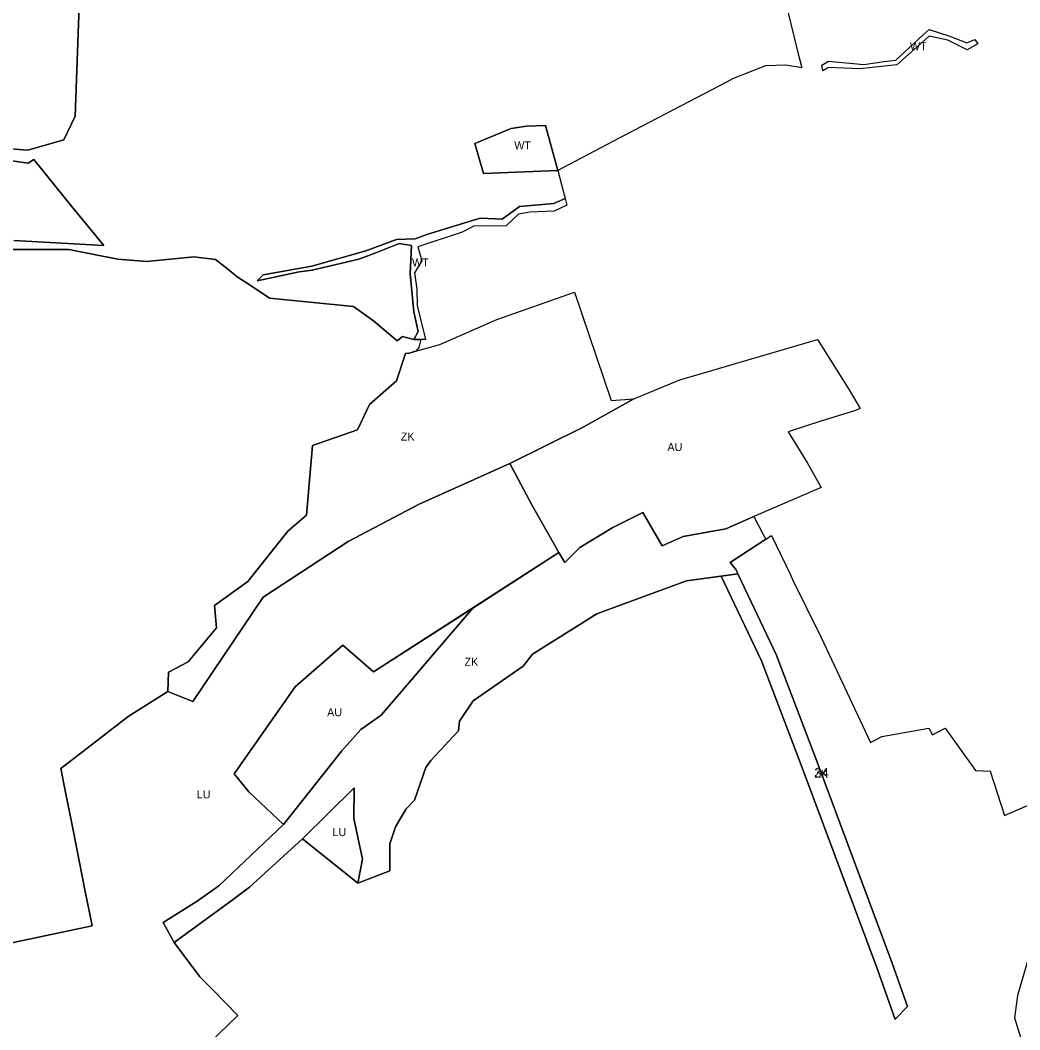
# Model space of a CAD drawing. Extents: x -521261 to -517465, y -1182764 to -1179456.
# Drawn here: x -520192 to -519568, y -1181503 to -1180873 of the extents above; entities that cross this region are included whole.
import ezdxf

# ---------------------------------------------------------------- set-up
doc = ezdxf.new("R2010")
doc.units = 0
for name, color, linetype in [('90640013', 7, 'Continuous'), ('90710013', 7, 'Continuous'), ('90710023', 7, 'Continuous'), ('90750013', 7, 'Continuous'), ('90770013', 7, 'Continuous'), ('ID_navrh', 7, 'Continuous')]:
    doc.layers.add(name, color=color, linetype=linetype)

msp = doc.modelspace()

# ---------------------------------------------------------------- linework, layer by layer
at = {"layer": '90640013'}
for points in [[(-519691.29, -1180904.57), (-519691.809, -1180901.025), (-519690.88, -1180900.43), (-519687.82, -1180898.6), (-519665.66, -1180900.58), (-519653.03, -1180898.83), (-519645.74, -1180897.87), (-519628.74, -1180882.19), (-519624.81, -1180878.8), (-519612.54, -1180882.66), (-519601.35, -1180887.12), (-519596.41, -1180884.93), (-519594.44, -1180887.7), (-519601.14, -1180891.37), (-519613.22, -1180885.44), (-519624.93, -1180882.92), (-519645.02, -1180900.87), (-519668.14, -1180903.39), (-519687.67, -1180902.45)], [(-519903.11, -1180968.58), (-519908.55, -1180949.89), (-519885.76, -1180940.63), (-519876.2, -1180939.15), (-519864.29, -1180938.71), (-519856.78, -1180966.81)], [(-519852.086, -1180984.372), (-519851.004, -1180988.421), (-519859, -1180992.12), (-519874.24, -1180992.85), (-519881.2, -1180994.07), (-519889.01, -1181001.36), (-519909.19, -1181001.61), (-519916.32, -1181005.27), (-519944.01, -1181014.53), (-519941.52, -1181023.22), (-519946.23, -1181030.81), (-519944.65, -1181040.94), (-519944.44, -1181051.2), (-519939.24, -1181072.38), (-519942.24, -1181072.32), (-519946.57, -1181072.34), (-519943.89, -1181067.29), (-519946.67, -1181055.07), (-519948.9, -1181031.28), (-519948.04, -1181013.6), (-519955.79, -1181012.41), (-519970.37, -1181018.3), (-519980.97, -1181022.1), (-520010.05, -1181029.02), (-520018.1, -1181030.01), (-520044.41, -1181035.77), (-520040.52, -1181031.99), (-520010.31, -1181026.46), (-519976.54, -1181017.03), (-519957.3, -1181009.97), (-519945.7, -1181009.39), (-519937.88, -1181006.53), (-519907.35, -1180997.12), (-519905.05, -1180996.64), (-519891.34, -1180997.12), (-519880.65, -1180989.37), (-519859.13, -1180987.38)]]:
    msp.add_lwpolyline(points, close=True, dxfattribs=at)
at = {"layer": '90710013'}
for points in [[(-520203.9, -1180952.83), (-520187.42, -1180954.15), (-520165.05, -1180947.64), (-520157.92, -1180932.93), (-520153.4, -1180806.35)], [(-519713.41, -1180866.64), (-519707.23, -1180891.41), (-519704.33, -1180902.77), (-519714.36, -1180901.07), (-519727.17, -1180901.52), (-519747.59, -1180909.52), (-519750.97, -1180911.49), (-519818.75, -1180946.927), (-519856.78, -1180966.81), (-519864.29, -1180938.71), (-519876.2, -1180939.15), (-519885.76, -1180940.63), (-519908.55, -1180949.89), (-519903.11, -1180968.58), (-519856.78, -1180966.81), (-519852.086, -1180984.372), (-519859.13, -1180987.38), (-519880.65, -1180989.37), (-519891.34, -1180997.12), (-519905.05, -1180996.64), (-519907.35, -1180997.12), (-519937.88, -1181006.53), (-519945.7, -1181009.39), (-519957.3, -1181009.97), (-519976.54, -1181017.03), (-520010.31, -1181026.46), (-520040.52, -1181031.99), (-520044.41, -1181035.77), (-520018.1, -1181030.01), (-520010.05, -1181029.02), (-519980.97, -1181022.1), (-519970.37, -1181018.3), (-519955.79, -1181012.41), (-519948.04, -1181013.6), (-519948.9, -1181031.28), (-519946.67, -1181055.07), (-519943.89, -1181067.29), (-519946.57, -1181072.34), (-519953.68, -1181070.49), (-519957.06, -1181073.24), (-519971.7, -1181060.63), (-519984.22, -1181051.71), (-520036.68, -1181046.43), (-520048.82, -1181038.46), (-520056.82, -1181033.22), (-520062.976, -1181028.253), (-520070.28, -1181022.36), (-520083.95, -1181020.65), (-520113.26, -1181023.55), (-520131.4, -1181022.11), (-520161.81, -1181016.06), (-520202.17, -1181016.05)], [(-520196.24, -1181010.47), (-520140.01, -1181013.64), (-520160.25, -1180989.16), (-520183.85, -1180959.97), (-520187.3, -1180962.26), (-520201.71, -1180960.23)]]:
    msp.add_lwpolyline(points, dxfattribs=at)
for points in [[(-520013.54, -1181182.09), (-520009.75, -1181138.53), (-519981.67, -1181128.85), (-519974.19, -1181113.01), (-519957.49, -1181098.06), (-519951.75, -1181081.08), (-519949.41, -1181080.84), (-519945.25, -1181079.6), (-519930.37, -1181075.45), (-519894.68, -1181059.82), (-519846.27, -1181042.69), (-519823.388, -1181110.412), (-519809.28, -1181109.36), (-519840.89, -1181127.16), (-519886.73, -1181149.7), (-519943.14, -1181175.07), (-519987.58, -1181198.4), (-520040.59, -1181233.21), (-520084.5, -1181298.3), (-520100.07, -1181292.11), (-520099.76, -1181280.17), (-520087.51, -1181273.69), (-520069.69, -1181252.35), (-520070.9, -1181238.45), (-520050.1, -1181223.4), (-520025.14, -1181191.93)], [(-519961.5, -1181387.25), (-519961.578, -1181404.089), (-519968.69, -1181406.86), (-519981.47, -1181411.84), (-519978.54, -1181396.94), (-519984.11, -1181371.39), (-519983.72, -1181352.35), (-520016.12, -1181384.16), (-520049.04, -1181414.3), (-520059.93, -1181422.38), (-520096.25, -1181448.83), (-520102.93, -1181436.39), (-520081.87, -1181423.03), (-520068.35, -1181413.48), (-520027.93, -1181375.27), (-519991.48, -1181329.17), (-519979.58, -1181315.88), (-519966.9, -1181306.97), (-519909.716, -1181240.018), (-519856.08, -1181205.45), (-519852.38, -1181211.59), (-519842.97, -1181202.29), (-519822.38, -1181189.69), (-519803.6, -1181180.37), (-519791.66, -1181201.16), (-519778.56, -1181195.39), (-519751.87, -1181190.47), (-519734.37, -1181182.89), (-519728.68, -1181193.73), (-519726.953, -1181197.019), (-519749.06, -1181211.51), (-519745.48, -1181216.27), (-519744.35, -1181218.67), (-519776.47, -1181223), (-519821.08, -1181239.47), (-519832.32, -1181243.68), (-519872.54, -1181268.79), (-519878.23, -1181276.31), (-519909.44, -1181297.97), (-519918, -1181310.57), (-519918.79, -1181316.7), (-519936.01, -1181335.15), (-519939.03, -1181339.56), (-519946.1, -1181359.91), (-519951.3, -1181365.5), (-519958.05, -1181376.65)]]:
    msp.add_lwpolyline(points, close=True, dxfattribs=at)
at = {"layer": '90710023'}
msp.add_lwpolyline([(-519729.514, -1181273.031), (-519754.759, -1181220.073), (-519744.35, -1181218.67), (-519720.31, -1181269.1), (-519695.05, -1181335.72), (-519648.02, -1181461.78), (-519638.47, -1181488.85), (-519646.12, -1181496.81), (-519646.234, -1181496.9), (-519657.42, -1181465.191), (-519704.41, -1181339.24)], close=True, dxfattribs=at)
at = {"layer": '90750013'}
for points in [[(-520201.71, -1180960.23), (-520187.3, -1180962.26), (-520183.85, -1180959.97), (-520160.25, -1180989.16), (-520140.01, -1181013.64), (-520196.24, -1181010.47)], [(-520202.17, -1181016.05), (-520161.81, -1181016.06), (-520131.4, -1181022.11), (-520113.26, -1181023.55), (-520083.95, -1181020.65), (-520070.28, -1181022.36), (-520062.976, -1181028.253), (-520056.82, -1181033.22), (-520048.82, -1181038.46), (-520036.68, -1181046.43), (-519984.22, -1181051.71), (-519971.7, -1181060.63), (-519957.06, -1181073.24), (-519953.68, -1181070.49), (-519946.57, -1181072.34), (-519942.24, -1181072.32), (-519943.52, -1181077.33), (-519945.25, -1181079.6), (-519949.41, -1181080.84), (-519951.75, -1181081.08), (-519957.49, -1181098.06), (-519974.19, -1181113.01), (-519981.67, -1181128.85), (-520009.75, -1181138.53), (-520013.54, -1181182.09), (-520025.14, -1181191.93), (-520050.1, -1181223.4), (-520070.9, -1181238.45), (-520069.69, -1181252.35), (-520087.51, -1181273.69), (-520099.76, -1181280.17), (-520100.07, -1181292.11), (-520124.95, -1181307.73), (-520150.71, -1181327.64), (-520166.98, -1181340.15), (-520164.29, -1181353.89), (-520159.29, -1181378.66), (-520151.63, -1181417.07), (-520148.84, -1181431.11), (-520147.36, -1181438.44), (-520216.32, -1181452.99)], [(-520079.5, -1181516.84), (-520056.39, -1181494.56), (-520072.1, -1181478.37), (-520080.04, -1181470.38), (-520096.25, -1181448.83), (-520059.93, -1181422.38), (-520049.04, -1181414.3), (-520016.12, -1181384.16), (-519981.47, -1181411.84), (-519968.69, -1181406.86), (-519961.578, -1181404.089), (-519961.5, -1181387.25), (-519958.05, -1181376.65), (-519951.3, -1181365.5), (-519946.1, -1181359.91), (-519939.03, -1181339.56), (-519936.01, -1181335.15), (-519918.79, -1181316.7), (-519918, -1181310.57), (-519909.44, -1181297.97), (-519878.23, -1181276.31), (-519872.54, -1181268.79), (-519832.32, -1181243.68), (-519821.08, -1181239.47), (-519776.47, -1181223), (-519754.759, -1181220.073), (-519729.514, -1181273.031), (-519704.41, -1181339.24), (-519657.42, -1181465.191), (-519646.234, -1181496.9), (-519646.12, -1181496.81), (-519638.47, -1181488.85), (-519648.02, -1181461.78), (-519695.05, -1181335.72), (-519720.31, -1181269.1), (-519744.35, -1181218.67), (-519745.48, -1181216.27), (-519749.06, -1181211.51), (-519726.953, -1181197.019), (-519723.4, -1181194.69), (-519711.37, -1181219.26), (-519710.22, -1181222.14), (-519692.36, -1181258.5), (-519661.58, -1181324.04), (-519654.54, -1181320.25), (-519625.19, -1181315.02), (-519622.89, -1181319.19), (-519615.01, -1181315.14), (-519595.9, -1181341.38), (-519586.91, -1181341.86), (-519577.82, -1181369.5), (-519560.15, -1181361.95)], [(-519560.34, -1181449.96), (-519569.85, -1181481.93), (-519571.73, -1181495.99), (-519569.38, -1181503.52), (-519567.26, -1181509.91), (-519574.763, -1181519.484), (-519573.589, -1181529.416), (-519576.305, -1181549.79), (-519588.994, -1181602.792), (-519590.98, -1181630.018), (-519590.97, -1181653.833), (-519587.026, -1181680.322), (-519572.226, -1181713.022), (-519551.44, -1181777.767)]]:
    msp.add_lwpolyline(points, dxfattribs=at)
for points in [[(-519671.54, -1181116.85), (-519692.44, -1181123.38), (-519712.94, -1181129.93), (-519700.84, -1181149.53), (-519692.32, -1181164.66), (-519734.37, -1181182.89), (-519751.87, -1181190.47), (-519778.56, -1181195.39), (-519791.66, -1181201.16), (-519803.6, -1181180.37), (-519822.38, -1181189.69), (-519842.97, -1181202.29), (-519852.38, -1181211.59), (-519856.08, -1181205.45), (-519872.92, -1181175.6), (-519886.73, -1181149.7), (-519840.89, -1181127.16), (-519809.28, -1181109.36), (-519780.6, -1181097.51), (-519739.3, -1181085.44), (-519694.53, -1181072.36), (-519674.88, -1181103.81), (-519667.99, -1181115.44)], [(-519971.69, -1181279.96), (-519909.716, -1181240.018), (-519966.9, -1181306.97), (-519979.58, -1181315.88), (-519991.48, -1181329.17), (-520027.93, -1181375.27), (-520038.45, -1181365.21), (-520049.55, -1181354.85), (-520058.68, -1181343.58), (-520020.61, -1181289.25), (-519990.97, -1181263.2)]]:
    msp.add_lwpolyline(points, close=True, dxfattribs=at)
at = {"layer": '90770013'}
for points in [[(-520203.9, -1180952.83), (-520202.96, -1180943.49), (-520212.94, -1180946.42), (-520219.04, -1180948.87), (-520227.61, -1180952.85), (-520260.64, -1180952.48), (-520300.29, -1180947.88), (-520344.99, -1180950.96), (-520344.3, -1180943.96), (-520347.18, -1180922.08), (-520360, -1180918.29), (-520377.28, -1180904.27), (-520373.63, -1180892.94), (-520376.27, -1180881.41), (-520440.58, -1180853.57), (-520296.21, -1180829.93), (-520153.4, -1180806.35), (-520157.92, -1180932.93), (-520165.05, -1180947.64), (-520187.42, -1180954.15)], [(-519983.72, -1181352.35), (-519984.11, -1181371.39), (-519978.54, -1181396.94), (-519981.47, -1181411.84), (-520016.12, -1181384.16)]]:
    msp.add_lwpolyline(points, close=True, dxfattribs=at)
msp.add_lwpolyline([(-520216.32, -1181452.99), (-520147.36, -1181438.44), (-520148.84, -1181431.11), (-520151.63, -1181417.07), (-520159.29, -1181378.66), (-520164.29, -1181353.89), (-520166.98, -1181340.15), (-520150.71, -1181327.64), (-520124.95, -1181307.73), (-520100.07, -1181292.11), (-520084.5, -1181298.3), (-520040.59, -1181233.21), (-519987.58, -1181198.4), (-519943.14, -1181175.07), (-519886.73, -1181149.7), (-519872.92, -1181175.6), (-519856.08, -1181205.45), (-519971.69, -1181279.96), (-519990.97, -1181263.2), (-520020.61, -1181289.25), (-520058.68, -1181343.58), (-520049.55, -1181354.85), (-520038.45, -1181365.21), (-520027.93, -1181375.27), (-520068.35, -1181413.48), (-520081.87, -1181423.03), (-520102.93, -1181436.39), (-520096.25, -1181448.83), (-520080.04, -1181470.38), (-520072.1, -1181478.37), (-520056.39, -1181494.56), (-520079.5, -1181516.84)], dxfattribs=at)

# ---------------------------------------------------------------- texts
at = {"layer": '90640013'}
for rotation, p in [(360, (-519636.887, -1180891.685)), (0, (-519883.878, -1180953.645)), (360, (-519947.707, -1181026.749))]:
    msp.add_text('WT', height=5, rotation=rotation, dxfattribs=at).set_placement(p)
at = {"layer": '90710013'}
for p in [(-519954.675, -1181135.429), (-519914.942, -1181276.102)]:
    msp.add_text('ZK', height=5, rotation=360, dxfattribs=at).set_placement(p)
at = {"layer": '90710023'}
msp.add_text('ZK', height=5, rotation=360, dxfattribs=at).set_placement((-519696.614, -1181345.864))
at = {"layer": '90750013'}
for p in [(-519788.262, -1181141.975), (-520000.679, -1181307.644)]:
    msp.add_text('AU', height=5, rotation=0, dxfattribs=at).set_placement(p)
at = {"layer": '90770013'}
for p in [(-520082.03, -1181358.885), (-519997.33, -1181382.441)]:
    msp.add_text('LU', height=5, rotation=0, dxfattribs=at).set_placement(p)
at = {"layer": 'ID_navrh'}
msp.add_text('34', height=6, rotation=360, dxfattribs=at).set_placement((-519696.614, -1181345.864))

doc.saveas('drawing.dxf')
